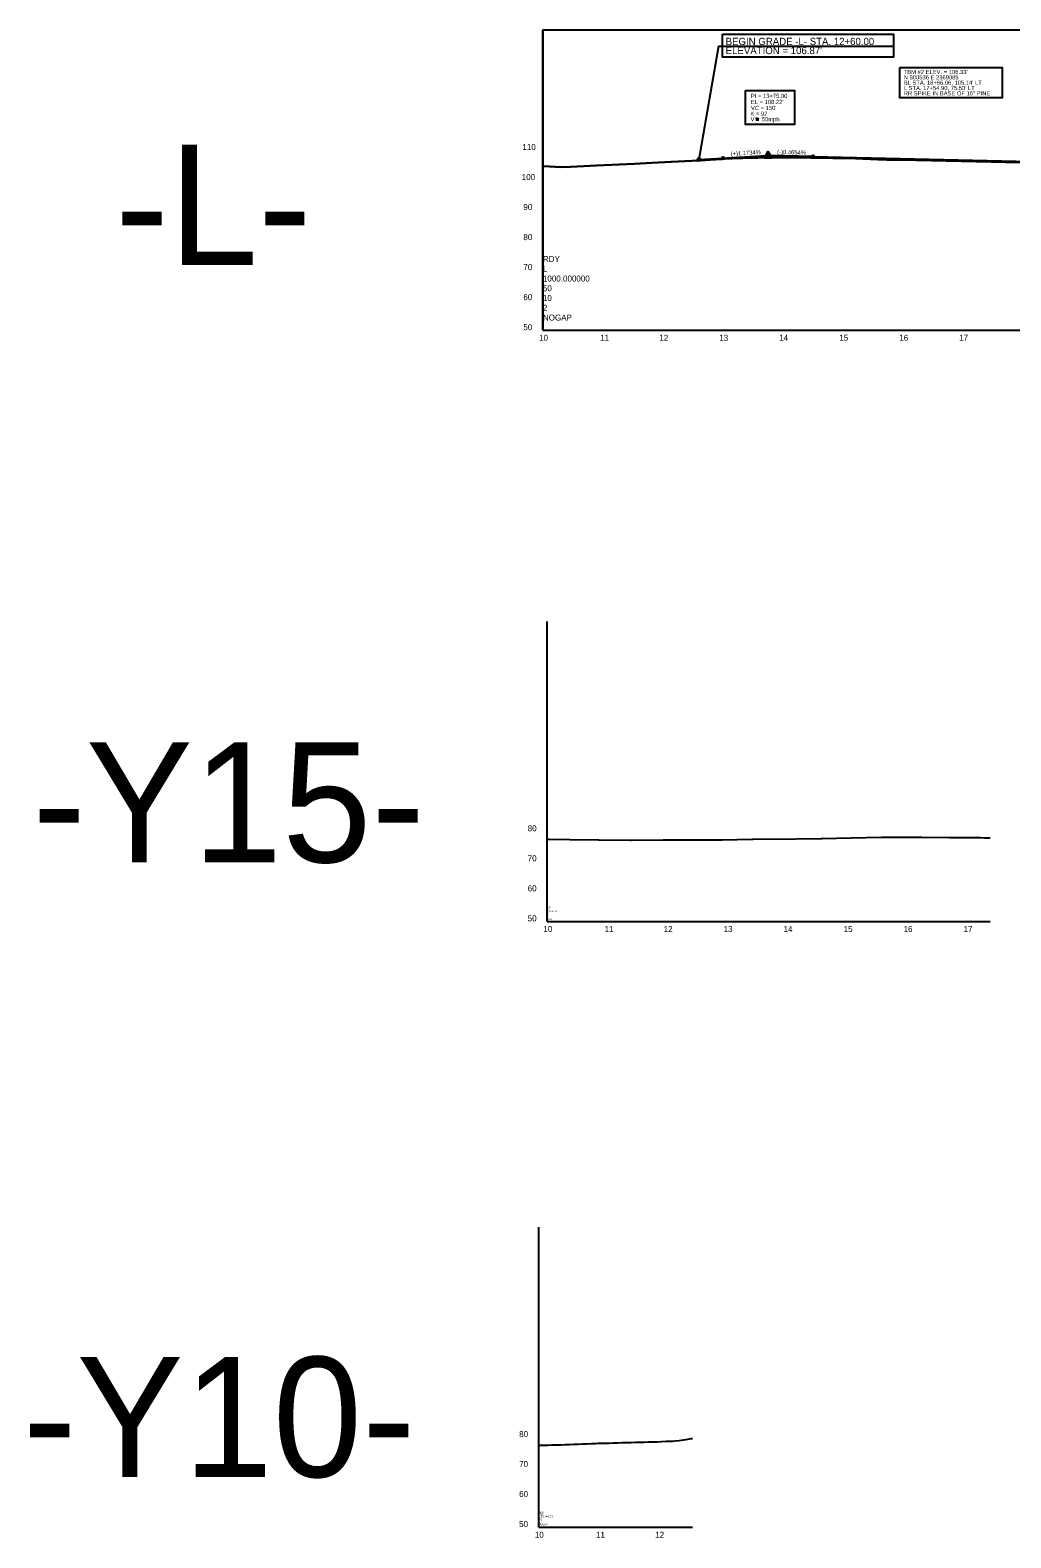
# Model space of a CAD drawing. Extents: x 2366464 to 2375718, y 801842 to 804354.
# Drawn here: x 2366464 to 2368098, y 801842 to 804354 of the extents above; entities that cross this region are included whole.
import ezdxf

# ---------------------------------------------------------------- set-up
doc = ezdxf.new("R2010")
doc.units = 0
for name, color, linetype in [('Default', 7, 'Continuous'), ('Exist Profile Cell', 7, 'Continuous'), ('Exist Vertical Profile Ground Line', 7, 'Continuous'), ('Exist Vertical Profile Horizontal Axis Label Major', 7, 'Continuous'), ('Exist Vertical Profile Vertical Axis Label', 7, 'Continuous'), ('Prop Grid Mask', 7, 'Continuous'), ('Prop PFL VPI Symbol CELL', 7, 'Continuous'), ('Prop Vertical Profile Curve Label', 7, 'Continuous'), ('Prop Vertical Profile Grade', 7, 'Continuous'), ('Prop Vertical Profile Grade Label', 7, 'Continuous'), ('Prop VPI Label', 7, 'Continuous'), ('Scratch_Level_5', 7, 'Continuous'), ('Sheet Layout Profile Border Port 1', 7, 'Continuous')]:
    doc.layers.add(name, color=color, linetype=linetype)

# ---------------------------------------------------------------- blocks, each defined once
blk = doc.blocks.new('Profile VPI Symbol')
at = {"layer": 'Prop PFL VPI Symbol CELL'}
for p, q in [((-0.001, 0.147), (-0.13, -0.077)), ((-0.001, 0.147), (0.129, -0.077)), ((-0.13, -0.077), (0.129, -0.077))]:
    blk.add_line(p, q, dxfattribs=at)
for radius in [0.035, 0.024]:
    blk.add_circle((-0.001, -0.003), radius, dxfattribs=at)

msp = doc.modelspace()

# ---------------------------------------------------------------- linework, layer by layer
at = {"layer": 'Exist Profile Cell'}
for p, q in [((2367318, 803854), (2367318, 804354)), ((2367318, 803854), (2374481.8, 803854)), ((2367318, 803854), (2367318, 803854)), ((2367325.2, 802869.1), (2367325.2, 803369.1)), ((2367325.2, 802869.1), (2368063.3, 802869.1)), ((2367325.2, 802869.1), (2367325.2, 802869.1)), ((2367311, 801859.9), (2367311, 802359.9)), ((2367311, 801859.9), (2367567, 801859.9)), ((2367311, 801859.9), (2367311, 801859.9))]:
    msp.add_line(p, q, dxfattribs=at)
at = {"layer": 'Exist Vertical Profile Ground Line'}
for points in [[(2367318, 804128.3), (2367318.4, 804128.3), (2367319.6, 804128.2), (2367320, 804128.2), (2367347.2, 804126.2), (2367364.3, 804127), (2367407, 804129.3), (2367470.4, 804131.9), (2367499.2, 804133.4), (2367531.7, 804135.3), (2367532.2, 804135.3), (2367588.1, 804138.2), (2367601.1, 804139.1), (2367613.6, 804139.8), (2367615.4, 804140), (2367626.1, 804140.6), (2367632.8, 804141), (2367638.6, 804141.2), (2367651.1, 804141.5), (2367663.6, 804141.8), (2367676.1, 804142.2), (2367683.7, 804142.4), (2367684.6, 804142.4), (2367686.1, 804142.4), (2367688.6, 804142.4), (2367701.1, 804142.4), (2367713.6, 804142.4), (2367726.1, 804142.4), (2367735.2, 804142.4), (2367738.6, 804142.4), (2367751.1, 804142.2), (2367763.6, 804142.1), (2367776.1, 804142), (2367784, 804141.9), (2367784.6, 804141.9), (2367788.6, 804141.8), (2367801.1, 804141.5), (2367813.6, 804141.2), (2367826.1, 804140.8), (2367838.9, 804140.5), (2367851.1, 804140.1), (2367863.6, 804139.7), (2367876.1, 804139.3), (2367891.1, 804138.8), (2367939.5, 804138), (2367940.2, 804138), (2367989.5, 804136.8), (2367990, 804136.8), (2367990.4, 804136.8), (2368039.7, 804135.7), (2368040.5, 804135.7), (2368088.9, 804134.6), (2368089.7, 804134.6), (2368138.2, 804134.2)], [(2367325.2, 803006.3), (2367328.2, 803006.2), (2367362.8, 803005.7), (2367410.6, 803005.1), (2367411.3, 803005.1), (2367463.4, 803004.8), (2367464, 803004.8), (2367465.1, 803004.8), (2367518.1, 803005.2), (2367518.7, 803005.2), (2367559.9, 803005.3), (2367560.8, 803005.3), (2367615.7, 803005.3), (2367616.9, 803005.3), (2367666.7, 803006.1), (2367667.1, 803006.1), (2367668.4, 803006.1), (2367739.8, 803007), (2367781.7, 803007.4), (2367782.2, 803007.4), (2367783, 803007.5), (2367831.3, 803008.5), (2367882.3, 803009.3), (2367882.8, 803009.3), (2367946, 803009.6), (2367949.4, 803009.5), (2367995.8, 803009), (2367996.7, 803009), (2368047.4, 803008.8), (2368054.1, 803008.7), (2368063.3, 803008.6)], [(2367311, 801996.5), (2367318.3, 801996.7), (2367325.6, 801996.9), (2367332.9, 801997.1), (2367340.3, 801997.3), (2367347.6, 801997.5), (2367354.9, 801997.7), (2367359.9, 801997.8), (2367360.5, 801997.9), (2367361.2, 801997.9), (2367362.2, 801997.9), (2367369.5, 801998.2), (2367376.8, 801998.5), (2367384.1, 801998.8), (2367391.4, 801999), (2367398.8, 801999.3), (2367406.1, 801999.6), (2367410.3, 801999.8), (2367410.7, 801999.8), (2367413.4, 801999.9), (2367420.7, 802000.1), (2367426.1, 802000.2), (2367428, 802000.3), (2367435.3, 802000.5), (2367442.6, 802000.7), (2367450, 802000.9), (2367456.8, 802001.1), (2367457.4, 802001.1), (2367464.6, 802001.3), (2367471.9, 802001.5), (2367479.3, 802001.6), (2367486.5, 802001.8), (2367493.8, 802002), (2367501.1, 802002.2), (2367501.6, 802002.2), (2367508.5, 802002.5), (2367515.8, 802002.8), (2367523.1, 802003.1), (2367530.4, 802003.4), (2367534.1, 802003.5), (2367537.7, 802003.9), (2367545, 802004.7), (2367551.9, 802005.5), (2367552.6, 802005.6), (2367559.7, 802006.8), (2367565, 802007.7), (2367565.8, 802007.9), (2367566.5, 802008), (2367567, 802007.9)]]:
    msp.add_lwpolyline(points, dxfattribs=at)
at = {"layer": 'Prop Grid Mask'}
for points in [[(2367617.4, 804347.5), (2367901.9, 804347.5), (2367901.9, 804308.8), (2367617.4, 804308.8)], [(2367912.5, 804291.5), (2368082.9, 804291.5), (2368082.9, 804241.3), (2367912.5, 804241.3)], [(2367655.7, 804253.3), (2367737, 804253.3), (2367737, 804196.6), (2367655.7, 804196.6)]]:
    msp.add_lwpolyline(points, close=True, dxfattribs=at)
at = {"layer": 'Prop Vertical Profile Curve Label'}
for p, q in [((2367672.9, 804205.6), (2367677.7, 804205.6)), ((2367672.9, 804204.6), (2367677.7, 804204.6)), ((2367677.7, 804205.6), (2367673, 804207.6))]:
    msp.add_line(p, q, dxfattribs=at)
for centre in [(2367618, 804140.7), (2367768, 804143.3)]:
    msp.add_circle(centre, 2.25, dxfattribs=at)
at = {"layer": 'Prop Vertical Profile Grade'}
for p, q in [((2367768, 804143.3), (2368183, 804133.7)), ((2367578, 804138.3), (2367618, 804140.7))]:
    msp.add_line(p, q, dxfattribs=at)
msp.add_spline([(2367618, 804140.7), (2367621, 804140.9), (2367624, 804141), (2367627, 804141.2), (2367630, 804141.3), (2367633, 804141.5), (2367636, 804141.6), (2367639, 804141.8), (2367642, 804141.9), (2367645, 804142.1), (2367648, 804142.2), (2367651, 804142.3), (2367654, 804142.4), (2367657, 804142.6), (2367660, 804142.7), (2367663, 804142.8), (2367666, 804142.9), (2367669, 804143), (2367672, 804143.1), (2367675, 804143.1), (2367678, 804143.2), (2367681, 804143.3), (2367684, 804143.4), (2367687, 804143.4), (2367690, 804143.5), (2367693, 804143.5), (2367696, 804143.6), (2367699, 804143.6), (2367702, 804143.7), (2367705, 804143.7), (2367708, 804143.7), (2367711, 804143.8), (2367714, 804143.8), (2367717, 804143.8), (2367720, 804143.8), (2367723, 804143.8), (2367726, 804143.8), (2367729, 804143.8), (2367732, 804143.8), (2367735, 804143.8), (2367738, 804143.8), (2367741, 804143.8), (2367744, 804143.7), (2367747, 804143.7), (2367750, 804143.7), (2367753, 804143.6), (2367756, 804143.6), (2367759, 804143.5), (2367762, 804143.5), (2367765, 804143.4), (2367768, 804143.3)], degree=3, dxfattribs=at)
at = {"layer": 'Prop VPI Label'}
for p, q in [((2367610.4, 804327.1), (2367578, 804138.3)), ((2367610.4, 804327.1), (2367901.3, 804327.1)), ((2367618, 804140.7), (2367690.2, 804144.9)), ((2367768, 804143.3), (2367695.7, 804145))]:
    msp.add_line(p, q, dxfattribs=at)
for centre in [(2367693, 804145.1), (2367578, 804138.3)]:
    msp.add_circle(centre, 2.75, dxfattribs=at)
at = {"layer": 'Scratch_Level_5'}
for p, q in [((2367668, 804142.9), (2367668, 804142.9)), ((2367668, 804142.9), (2367668, 804142.9)), ((2367868, 804140.2), (2367868, 804140.2))]:
    msp.add_line(p, q, dxfattribs=at)
msp.add_lwpolyline([(2367318, 804127.7), (2367318.4, 804127.7), (2367319.6, 804127.6), (2367320, 804127.6), (2367347.2, 804125.6), (2367364.3, 804126.4), (2367407, 804128.6), (2367470.4, 804131.3), (2367499.2, 804132.8), (2367531.8, 804134.6), (2367532.3, 804134.7), (2367588.1, 804137.6), (2367613.6, 804139.2), (2367615.4, 804139.3), (2367626.1, 804140), (2367632.8, 804140.4), (2367638.6, 804140.5), (2367651.1, 804140.9), (2367663.6, 804141.2), (2367676.1, 804141.5), (2367683.7, 804141.8), (2367684.6, 804141.8), (2367686.1, 804141.8), (2367688.6, 804141.8), (2367701.1, 804141.8), (2367713.6, 804141.8), (2367726.1, 804141.8), (2367735.2, 804141.8), (2367738.6, 804141.7), (2367751.1, 804141.6), (2367763.6, 804141.5), (2367776.1, 804141.4), (2367784, 804141.3), (2367784.6, 804141.3), (2367788.6, 804141.2), (2367801.1, 804140.9), (2367813.6, 804140.5), (2367838.9, 804139.9), (2367851.1, 804139.5), (2367863.6, 804139.1), (2367876.1, 804138.6), (2367891.1, 804138.2), (2367939.5, 804137.3), (2367940.2, 804137.3), (2367990, 804136.2), (2367990.4, 804136.1), (2368039.7, 804135), (2368040.5, 804135), (2368088.8, 804134), (2368089.7, 804133.9), (2368138.2, 804133.6)], dxfattribs=at)
at = {"layer": 'Sheet Layout Profile Border Port 1'}
msp.add_lwpolyline([(2367318, 803854), (2368718, 803854), (2368718, 804354), (2367318, 804354)], close=True, dxfattribs=at)

# ---------------------------------------------------------------- block references
at = {"layer": 'Prop Grid Mask', "xscale": 50, "yscale": 50}
msp.add_blockref('Profile VPI Symbol', (2367693, 804145.1), dxfattribs=at)

# ---------------------------------------------------------------- texts
at = {"layer": 'Default'}
for s, p in [('-L-', (2366605.6, 803963)), ('-Y15-', (2366467.4, 802967.7)), ('-Y10-', (2366451.8, 801943.7))]:
    msp.add_text(s, height=200, dxfattribs=at).set_placement(p)
at = {"layer": 'Exist Profile Cell'}
for s, height, p in [('RDY', 10, (2367318, 803967.7)), ('1000.000000', 10, (2367318, 803935.2)), ('L', 10, (2367318, 803951.5)), ('50', 10, (2367318, 803919)), ('2', 10, (2367318, 803886.5)), ('10', 10, (2367318, 803902.7)), ('NOGAP', 10, (2367318, 803870.2)), ('Y15', 2, (2367325.2, 802888.6)), ('1000.000000', 2, (2367325.2, 802885.3)), ('RDY', 2, (2367325.2, 802891.8)), ('50', 2, (2367325.2, 802882.1)), ('10', 2, (2367325.2, 802878.8)), ('2', 2, (2367325.2, 802875.6)), ('NOGAP', 2, (2367325.2, 802872.3)), ('Y10', 3, (2367311, 801879.5)), ('RDY', 3, (2367311, 801882.8)), ('50', 3, (2367311, 801873)), ('2', 3, (2367311, 801866.5)), ('1000.000000', 3, (2367311, 801876.3)), ('10', 3, (2367311, 801869.7)), ('NOGAP', 3, (2367311, 801863.2))]:
    msp.add_text(s, height=height, dxfattribs=at).set_placement(p)
at = {"layer": 'Exist Vertical Profile Horizontal Axis Label Major'}
for s, p in [('10', (2367311.6, 803836.5)), ('11', (2367413.4, 803836.5)), ('12', (2367511.9, 803836.5)), ('13', (2367611.8, 803836.5)), ('14', (2367711.6, 803836.5)), ('15', (2367811.7, 803836.5)), ('16', (2367911.7, 803836.5)), ('17', (2368011.5, 803836.5)), ('10', (2367318.8, 802851.6)), ('11', (2367420.7, 802851.6)), ('12', (2367519.2, 802851.6)), ('13', (2367619, 802851.6)), ('14', (2367718.9, 802851.6)), ('15', (2367819, 802851.6)), ('16', (2367918.9, 802851.6)), ('17', (2368018.8, 802851.6)), ('10', (2367304.6, 801842.4)), ('11', (2367406.4, 801842.4)), ('12', (2367505, 801842.4))]:
    msp.add_text(s, height=10, dxfattribs=at).set_placement(p)
at = {"layer": 'Exist Vertical Profile Vertical Axis Label'}
for s, p in [('110', (2367283.8, 804154.2)), ('100', (2367282.6, 804104.2)), ('90', (2367285.4, 804054.2)), ('80', (2367285.4, 804004.2)), ('70', (2367285.4, 803954.2)), ('60', (2367285.4, 803904.2)), ('50', (2367285.4, 803854.2)), ('80', (2367292.6, 803019.3)), ('70', (2367292.6, 802969.3)), ('60', (2367292.6, 802919.3)), ('50', (2367292.6, 802869.3)), ('80', (2367278.4, 802010.2)), ('70', (2367278.4, 801960.2)), ('60', (2367278.4, 801910.2)), ('50', (2367278.4, 801860.2))]:
    msp.add_text(s, height=10, dxfattribs=at).set_placement(p)
at = {"layer": 'Prop Vertical Profile Curve Label'}
for s, p in [('K = 92', (2367663.8, 804211.3)), ("VC = 150'", (2367664.6, 804220.9)), ('V', (2367664, 804202.1)), ('50mph', (2367682.7, 804202.2))]:
    msp.add_text(s, height=7, dxfattribs=at).set_placement(p)
at = {"layer": 'Prop Vertical Profile Grade Label'}
for s, rotation, p in [('(+)1.1734%', 3.3577, (2367631.1, 804144.5)), ('(-)0.4654%', 358.6668, (2367708.3, 804147.7))]:
    msp.add_text(s, height=7, rotation=rotation, dxfattribs=at).set_placement(p)
at = {"layer": 'Prop VPI Label'}
for s, height, p in [('BEGIN GRADE -L- STA. 12+60.00', 12, (2367622.5, 804329.2)), ("ELEVATION = 106.87'", 12, (2367622.5, 804314)), ("TBM #2 ELEV. = 106.33'", 7, (2367919.2, 804280.8)), ('N 800536 E 2369085', 7, (2367919.2, 804271.9)), ("BL STA. 18+66.06, 105.14' LT", 7, (2367919.2, 804263)), ('PI = 13+75.00', 7, (2367664.6, 804240.9)), ("L STA. 17+54.90, 75.50' LT", 7, (2367919.2, 804254.1)), ('RR SPIKE IN BASE OF 16" PINE', 7, (2367919.2, 804245.3)), ("EL = 108.22'", 7, (2367664.6, 804230.9))]:
    msp.add_text(s, height=height, dxfattribs=at).set_placement(p)

doc.saveas('drawing.dxf')
